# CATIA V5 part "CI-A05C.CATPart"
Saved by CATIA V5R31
Part number: CI-A05C
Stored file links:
  C:\Users\simone\Dropbox\3DTECH\Cassina - Catalogo Custom Interiors\MODELLI 3D\DEFINITIVI\ESPORTATI\CI-A05C SEDIA OUTDOOR CON BRACCIOLI\CI-A05C.CATPart

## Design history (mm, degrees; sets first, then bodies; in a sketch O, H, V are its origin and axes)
Set1
  Point1 "Point.1": stored without definition
  DatumCurve1 "Curve.1"
  DatumCurve2 "Curve.2"
  DatumCurve3 "Curve.3"
  DatumCurve4 "Curve.4"
Body1 "Solid13" (main body)
  Solid1: solid without history
Body2 "Solid26"
  Solid2: solid without history
Body3 "Solid28"
  Solid3: solid without history
Body4 "Solid35"
  Solid4: solid without history
Body5 "Solid36"
  Solid5: solid without history
Body6 "Solid45"
  Solid6: solid without history
Body7 "Solid46"
  Solid7: solid without history
Body8 "Solido47"
  Solid8: solid without history
Body9 "piedini frontali"
  Solid9: solid without history
Body10 "piedini retro"
  Solid10: solid without history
